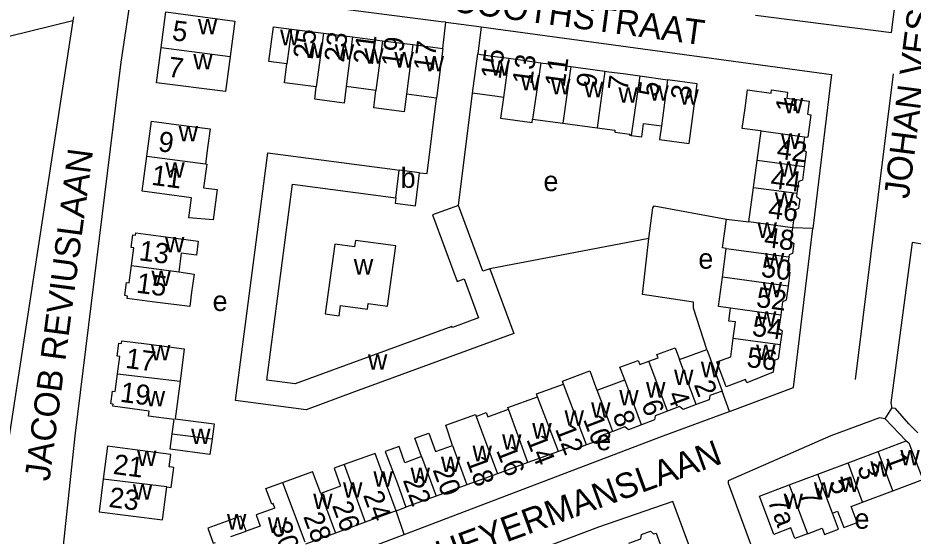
# Model space of a CAD drawing. Extents: x 161258 to 163262, y 380749 to 382054.
# Drawn here: x 161562.6 to 161740.8, y 381480.1 to 381583.2 of the extents above; entities that cross this region are included whole.
import ezdxf

# ---------------------------------------------------------------- set-up
doc = ezdxf.new("R2010")
doc.units = 0
for name, color, linetype in [('BLT_Basislijn', 7, 'Continuous'), ('BLT_Bebouwing', 7, 'Continuous'), ('BLT_Centroide', 7, 'Continuous'), ('BLT_Huisnummer', 7, 'Continuous'), ('BLT_Huisnummer_ tussenligend', 7, 'Continuous'), ('BLT_Onderverdeling_panden', 7, 'Continuous'), ('BLT_Straatnaam', 7, 'Continuous')]:
    doc.layers.add(name, color=color, linetype=linetype)

msp = doc.modelspace()

# ---------------------------------------------------------------- linework, layer by layer
at = {"layer": 'BLT_Basislijn'}
for p, q in [((161573.62, 381583.36), (161573.5, 381582.58)), ((161647.18, 381577.07), (161647.76, 381582.3)), ((161654.8, 381581.39), (161654.12, 381576)), ((161736.86, 381572.03), (161729.29, 381511.22)), ((161650.31, 381545.88), (161653.06, 381568.21)), ((161720.87, 381541.28), (161716.78, 381541.4)), ((161688.2, 381539.29), (161656.55, 381533.28)), ((161704.28, 381504.89), (161702.82, 381508.93)), ((161735.27, 381503.44), (161736.56, 381505.52)), ((161739.46, 381499.04), (161735.27, 381503.44)), ((161637.9, 381485.08), (161639.84, 381485.84)), ((161639.49, 381480.37), (161637.9, 381485.08))]:
    msp.add_line(p, q, dxfattribs=at)
for points in [[(161709.43, 381583.72), (161736.54, 381580.27), (161740.2, 381609.45)], [(161647.76, 381582.3), (161646.86, 381582.41), (161591.08, 381589.63), (161587.77, 381589.77), (161586.23, 381588.91), (161584.89, 381586.68), (161583.08, 381574.39), (161573.92, 381500), (161570.58, 381468.89), (161570.42, 381465.8), (161572.24, 381462.03), (161574.18, 381460.03), (161576.58, 381458.66), (161578.81, 381458.22), (161583.37, 381458.7), (161593.26, 381463), (161639.49, 381480.37)], [(161573.5, 381582.58), (161530.8, 381572.09), (161520.53, 381568.26), (161516.5, 381566.33)], [(161573.5, 381582.58), (161560.8, 381500), (161558.43, 381477.88), (161556.99, 381466.34), (161552.69, 381452.74), (161550.87, 381443.13)], [(161647.76, 381582.3), (161653.89, 381581.52), (161654.8, 381581.39)], [(161654.8, 381581.39), (161724.58, 381571.93), (161720.93, 381541.79), (161720.87, 381541.28)], [(161642.56, 381552.35), (161644.05, 381552.23), (161645.9, 381567.19)], [(161688.2, 381539.29), (161689.02, 381545.36), (161689.23, 381545.81), (161703.66, 381543.16)], [(161704.28, 381504.89), (161716.98, 381509.66), (161720.87, 381541.28)], [(161699.74, 381517.22), (161697.12, 381525.43), (161697.11, 381526.63), (161686.95, 381528.13), (161688.2, 381539.29)], [(161793.03, 381529.1), (161792.29, 381529.24), (161754.8, 381536.11), (161740.64, 381538.46), (161736.37, 381506.61), (161736.56, 381505.52)], [(161639.49, 381480.37), (161640.36, 381480.7), (161691.05, 381500), (161703.66, 381504.66), (161704.28, 381504.89)], [(161741.75, 381500.63), (161739.94, 381502.39), (161737.34, 381505.48), (161736.56, 381505.52)], [(161735.27, 381503.44), (161734.11, 381503.59), (161724.44, 381500), (161704.01, 381491.08), (161703.96, 381490.64), (161712.68, 381466.99), (161712.83, 381466.59)], [(161701.85, 381462.93), (161692.96, 381486.95), (161678.18, 381481.89), (161623.33, 381461.17), (161623.17, 381460.48), (161624.21, 381455.92), (161632.42, 381433.68), (161632.51, 381433.43)]]:
    msp.add_lwpolyline(points, dxfattribs=at)
at = {"layer": 'BLT_Bebouwing'}
for p, q in [((161617.02, 381580.95), (161623.39, 381580.15)), ((161623.39, 381580.15), (161629.21, 381579.4)), ((161629.21, 381579.4), (161635.14, 381578.63)), ((161635.14, 381578.63), (161641.2, 381577.85)), ((161641.2, 381577.85), (161647.18, 381577.07)), ((161647.18, 381577.07), (161645.9, 381567.19)), ((161653.06, 381568.21), (161654.12, 381576)), ((161633.86, 381568.75), (161627.93, 381569.52)), ((161709.77, 381554.82), (161710.57, 381560.69)), ((161719.21, 381559.54), (161719.86, 381559.45)), ((161709.05, 381549.44), (161709.77, 381554.82)), ((161642.56, 381552.35), (161638.51, 381552.88)), ((161708.12, 381542.57), (161709.05, 381549.44)), ((161702.84, 381531.62), (161703.61, 381537.31)), ((161694.28, 381515.2), (161699.74, 381517.22)), ((161677.88, 381509.1), (161683.4, 381511.15)), ((161733.84, 381496.92), (161739.46, 381499.04)), ((161670.19, 381496.92), (161664.13, 381494.71)), ((161727.86, 381494.67), (161733.84, 381496.92)), ((161633.72, 381496.51), (161627.51, 381494.3)), ((161664.13, 381494.71), (161658.05, 381492.49)), ((161721.85, 381492.4), (161727.86, 381494.67)), ((161615.23, 381490.73), (161621.26, 381492.93)), ((161658.05, 381492.49), (161651.95, 381490.26)), ((161716.14, 381490.25), (161721.85, 381492.4)), ((161651.95, 381490.26), (161645.84, 381488.03)), ((161736.75, 381489.1), (161742.73, 381491.35)), ((161645.84, 381488.03), (161639.84, 381485.84)), ((161730.77, 381486.84), (161736.75, 381489.1)), ((161637.9, 381485.08), (161631.71, 381482.82)), ((161631.71, 381482.82), (161625.77, 381480.65)), ((161625.77, 381480.65), (161619.84, 381478.48))]:
    msp.add_line(p, q, dxfattribs=at)
for points in [[(161591.06, 381577.29), (161592, 381584.35), (161605.75, 381582.53), (161604.81, 381575.47)], [(161616.12, 381574.05), (161612.55, 381574.51), (161613.45, 381581.41), (161617.02, 381580.95)], [(161604.81, 381575.47), (161603.89, 381568.51), (161590.13, 381570.23), (161591.06, 381577.29)], [(161654.12, 381576), (161654.76, 381575.92), (161657.52, 381575.51), (161660.29, 381575.14)], [(161615.63, 381570.25), (161616.12, 381574.05)], [(161660.29, 381575.14), (161660.7, 381575.08), (161663.57, 381574.68), (161666.71, 381574.26)], [(161666.71, 381574.26), (161667.11, 381574.2), (161669.65, 381573.89), (161672.64, 381573.49)], [(161672.64, 381573.49), (161679.45, 381572.56)], [(161679.45, 381572.56), (161680.22, 381572.46), (161683.06, 381572.09), (161686.37, 381571.64)], [(161686.37, 381571.64), (161691.94, 381570.88)], [(161621.98, 381569.43), (161615.63, 381570.25)], [(161690.7, 381561.7), (161690.33, 381559.01), (161696.22, 381558.21), (161697.16, 381565.13), (161697.84, 381570.08), (161691.94, 381570.88)], [(161627.93, 381569.52), (161627.51, 381566.24), (161621.69, 381567), (161621.98, 381569.43)], [(161639.92, 381567.97), (161639.47, 381564.49), (161633.41, 381565.28), (161633.86, 381568.75)], [(161659.23, 381567.37), (161658.01, 381567.53), (161653.06, 381568.21)], [(161710.57, 381560.69), (161709.87, 381560.79), (161706.8, 381561.14), (161707.35, 381565.22), (161707.85, 381568.86), (161712.53, 381568.23), (161712.61, 381568.85), (161715.81, 381568.42), (161715.64, 381567.2), (161720.12, 381566.59), (161719.78, 381564.01), (161720.46, 381563.92), (161719.86, 381559.45)], [(161645.9, 381567.19), (161639.92, 381567.97)], [(161659.23, 381567.37), (161658.67, 381563.23), (161664.93, 381562.38), (161665.02, 381563.05)], [(161665.02, 381563.05), (161671.09, 381562.23)], [(161588.25, 381555.66), (161589.18, 381562.64), (161594.08, 381561.99), (161600.83, 381561.09), (161600.39, 381557.81), (161599.9, 381554.11)], [(161671.09, 381562.23), (161677.92, 381561.3)], [(161677.92, 381561.3), (161681.45, 381560.82), (161681.4, 381560.45), (161684.38, 381560.05), (161684.35, 381559.83), (161684.65, 381559.78)], [(161684.65, 381559.78), (161686.77, 381559.49), (161687.14, 381562.19), (161690.7, 381561.7)], [(161719.21, 381559.54), (161718.87, 381557.04), (161719.53, 381556.53), (161719.13, 381553.56)], [(161599.9, 381554.11), (161600.15, 381554.08), (161599.53, 381549.4), (161602.26, 381549.04), (161601.46, 381542.99), (161596.58, 381543.43), (161597.1, 381547.39), (161587.33, 381548.69), (161588.25, 381555.66)], [(161629.59, 381508.75), (161619.94, 381505.22), (161605.9, 381507.05), (161612.34, 381556.3), (161637.6, 381553), (161638.51, 381552.88)], [(161637.8, 381547.39), (161637.66, 381546.34), (161641.7, 381545.81), (161642.56, 381552.35)], [(161719.13, 381553.56), (161718.77, 381550.92), (161718, 381550.6), (161717.69, 381548.28)], [(161650.31, 381545.88), (161645.13, 381543.98), (161650, 381530.7), (161651.45, 381531.23), (161654.29, 381523.48), (161649.09, 381521.57), (161649, 381521.8), (161617.76, 381510.35), (161612.11, 381511.09), (161617.21, 381550.09), (161637.8, 381547.39)], [(161717.69, 381548.28), (161717.6, 381547.62), (161718.25, 381547.11), (161718, 381545.25), (161717.27, 381544.95), (161716.78, 381541.4)], [(161656.55, 381533.28), (161655.12, 381532.76), (161650.31, 381545.88)], [(161703.61, 381537.31), (161702.88, 381537.41), (161703.66, 381543.16)], [(161703.66, 381543.16), (161708.12, 381542.57)], [(161716.78, 381541.4), (161716.43, 381538.76), (161717.06, 381538.28), (161716.79, 381536.31), (161716.11, 381536.03), (161716.06, 381535.64)], [(161585.19, 381533.93), (161585.65, 381537.41), (161585.09, 381537.49), (161585.43, 381540.02), (161585.99, 381539.95), (161586.05, 381540.4), (161591.04, 381539.74), (161598.46, 381538.76), (161598.1, 381535.99), (161595.1, 381536.39), (161594.61, 381532.68)], [(161623.74, 381524.3), (161626.52, 381523.92), (161626.8, 381525.97), (161632.15, 381525.24), (161632.3, 381526.33), (161636.16, 381525.8), (161637.81, 381537.82), (161629.78, 381538.92), (161629.6, 381537.64), (161625.65, 381538.18), (161623.74, 381524.3)], [(161716.06, 381535.64), (161715.71, 381533.03), (161716.28, 381532.59), (161715.91, 381529.8)], [(161594.61, 381532.68), (161597.67, 381532.21), (161597.16, 381528.58), (161596.78, 381525.73), (161589.29, 381526.72), (161584.33, 381527.38), (161584.39, 381527.84), (161583.83, 381527.92), (161584.18, 381530.51), (161584.73, 381530.44), (161585.19, 381533.93)], [(161656.55, 381533.28), (161658.27, 381528.59), (161661.28, 381520.36), (161629.59, 381508.75)], [(161704.47, 381525.44), (161702.05, 381525.76), (161702.84, 381531.62)], [(161715.91, 381529.8), (161715.53, 381527), (161714.81, 381526.71), (161714.45, 381524.04)], [(161704.99, 381519.45), (161705.42, 381522.68), (161704.12, 381522.85), (161704.47, 381525.44)], [(161714.45, 381524.04), (161714.09, 381521.38), (161714.73, 381520.89), (161714.36, 381518.2)], [(161582.37, 381512.33), (161582.83, 381515.82), (161582.32, 381515.89), (161582.66, 381518.48), (161583.18, 381518.41), (161583.25, 381518.96), (161588.18, 381518.31), (161595.68, 381517.32), (161594.88, 381510.91)], [(161714.36, 381518.2), (161713.97, 381515.32), (161713.24, 381515.02), (161712.92, 381512.71), (161707.72, 381510.57), (161707.45, 381511.22), (161703.6, 381509.78), (161701.75, 381514.78), (161704.5, 381515.75), (161704.99, 381519.45)], [(161688.22, 381514.89), (161690.04, 381515.56), (161689.81, 381516.18), (161693.42, 381517.52), (161694.28, 381515.2)], [(161699.74, 381517.22), (161701.08, 381513.62), (161702.82, 381508.93)], [(161683.4, 381511.15), (161682.45, 381513.7), (161686.06, 381515.04), (161686.37, 381514.2), (161688.21, 381514.88)], [(161671.22, 381510.33), (161671, 381510.92), (161676.42, 381512.97), (161677.84, 381509.09), (161677.88, 381509.1)], [(161593.29, 381500.44), (161593.66, 381503.25), (161588.59, 381503.92), (161588.73, 381504.96), (161581.49, 381505.92), (161581.55, 381506.31), (161581.04, 381506.38), (161581.37, 381508.9), (161581.9, 381508.83), (161582.37, 381512.33)], [(161594.88, 381510.91), (161593.89, 381503.39), (161601.62, 381502.41), (161601.22, 381499.44)], [(161666.05, 381507.8), (161665.85, 381508.36), (161671.22, 381510.33)], [(161660.26, 381505.32), (161660.14, 381505.65), (161666.05, 381507.8)], [(161702.82, 381508.93), (161700.35, 381508.02), (161700.21, 381507.2), (161697.61, 381506.24)], [(161697.61, 381506.24), (161695.01, 381505.27), (161694.32, 381505.84), (161691.89, 381504.93)], [(161649.08, 381498.1), (161647.76, 381502.15), (161653.69, 381504.27), (161653.82, 381503.89)], [(161653.82, 381503.89), (161655.8, 381504.66), (161656.12, 381503.8), (161660.26, 381505.32)], [(161691.89, 381504.93), (161689.45, 381504.03), (161689.31, 381503.18), (161686.72, 381502.22)], [(161686.72, 381502.22), (161684.12, 381501.25), (161683.42, 381501.84), (161681.03, 381500.92)], [(161601.22, 381499.44), (161600.81, 381496.31), (161592.88, 381497.36), (161593.29, 381500.44)], [(161642.96, 381495.91), (161641.63, 381499.56), (161644.41, 381500.57), (161645.74, 381496.92), (161649.08, 381498.1)], [(161681.03, 381500.92), (161678.65, 381500), (161678.54, 381499.22), (161675.78, 381498.22)], [(161739.46, 381499.04), (161739.99, 381498.61), (161741.76, 381493.93), (161742.73, 381491.35)], [(161592.2, 381489.9), (161593.07, 381489.78), (161593.58, 381493.73), (161592.67, 381493.85), (161592.99, 381496.33), (161585.4, 381497.3), (161580.4, 381497.94), (161579.57, 381491.44)], [(161642.96, 381495.91), (161639.64, 381494.68), (161638.46, 381497.9), (161635.66, 381496.88), (161638.12, 381490.53), (161639.84, 381485.84)], [(161675.78, 381498.22), (161673.36, 381497.33), (161672.74, 381497.85), (161670.19, 381496.92)], [(161637.9, 381485.08), (161636.18, 381489.77), (161633.72, 381496.51)], [(161627.51, 381494.3), (161625.52, 381493.57), (161626.82, 381490.01), (161622.88, 381488.57)], [(161579.57, 381491.44), (161578.73, 381484.91), (161591.36, 381483.29), (161591.42, 381483.76), (161592.2, 381489.9)], [(161622.88, 381488.57), (161621.25, 381492.93)], [(161613.71, 381485.64), (161613.41, 381486.55), (161613.1, 381486.44), (161611.96, 381489.54), (161615.23, 381490.73)], [(161719.81, 381480.54), (161717.28, 381479.59), (161716.48, 381481.71), (161713.08, 381480.43), (161710.21, 381488.02), (161716.14, 381490.25)], [(161724.76, 381484.67), (161725.77, 381485.05), (161727, 381481.8), (161729.65, 381482.8), (161728.45, 381485.97), (161730.77, 381486.84)], [(161613.71, 381485.64), (161609.98, 381484.28), (161610.78, 381482.09)], [(161719.81, 381480.54), (161722.68, 381481.68), (161723.17, 381480.38), (161725.98, 381481.43), (161724.76, 381484.67)], [(161608.01, 381481.08), (161606.93, 381484.05), (161600.37, 381481.65), (161601.45, 381478.68), (161601.88, 381478.84)], [(161610.78, 381482.09), (161608.01, 381481.08)], [(161684.21, 381478.67), (161686.59, 381479.56), (161686.73, 381480.39), (161688.53, 381481.05), (161689.15, 381480.53), (161689.63, 381480.66), (161691.23, 381476.29)]]:
    msp.add_lwpolyline(points, dxfattribs=at)
at = {"layer": 'BLT_Onderverdeling_panden'}
for p, q in [((161617.02, 381580.95), (161616.12, 381574.05)), ((161623.39, 381580.15), (161621.98, 381569.43)), ((161629.21, 381579.4), (161627.93, 381569.52)), ((161591.06, 381577.29), (161604.81, 381575.47)), ((161635.14, 381578.63), (161633.86, 381568.75)), ((161641.2, 381577.85), (161639.92, 381567.97)), ((161660.29, 381575.14), (161659.23, 381567.37)), ((161666.71, 381574.26), (161665.02, 381563.05)), ((161672.64, 381573.49), (161671.09, 381562.23)), ((161679.45, 381572.56), (161677.92, 381561.3)), ((161686.37, 381571.64), (161684.65, 381559.78)), ((161691.94, 381570.88), (161690.7, 381561.7)), ((161710.57, 381560.69), (161719.21, 381559.54)), ((161588.25, 381555.66), (161599.9, 381554.11)), ((161719.13, 381553.56), (161709.77, 381554.82)), ((161637.8, 381547.39), (161638.51, 381552.88)), ((161709.05, 381549.44), (161717.69, 381548.28)), ((161716.78, 381541.4), (161708.12, 381542.57)), ((161703.61, 381537.31), (161716.06, 381535.64)), ((161585.19, 381533.93), (161594.61, 381532.68)), ((161715.91, 381529.8), (161702.84, 381531.62)), ((161714.45, 381524.04), (161704.47, 381525.44)), ((161704.99, 381519.45), (161714.36, 381518.2)), ((161691.89, 381504.93), (161688.21, 381514.88)), ((161697.61, 381506.24), (161694.28, 381515.2)), ((161582.37, 381512.33), (161594.88, 381510.91)), ((161686.72, 381502.22), (161683.4, 381511.15)), ((161675.78, 381498.22), (161671.22, 381510.33)), ((161670.19, 381496.92), (161666.05, 381507.8)), ((161681.03, 381500.92), (161677.88, 381509.1)), ((161653.82, 381503.89), (161658.05, 381492.49)), ((161664.13, 381494.71), (161660.26, 381505.32)), ((161593.29, 381500.44), (161601.22, 381499.44)), ((161649.08, 381498.1), (161651.95, 381490.26)), ((161736.75, 381489.1), (161733.84, 381496.92)), ((161642.96, 381495.91), (161645.84, 381488.03)), ((161627.51, 381494.3), (161631.71, 381482.82)), ((161730.77, 381486.84), (161727.86, 381494.67)), ((161592.2, 381489.9), (161579.57, 381491.44)), ((161724.76, 381484.67), (161721.85, 381492.4)), ((161615.23, 381490.73), (161619.67, 381478.94)), ((161716.14, 381490.25), (161719.81, 381480.54)), ((161622.88, 381488.57), (161625.77, 381480.65))]:
    msp.add_line(p, q, dxfattribs=at)
msp.add_lwpolyline([(161604.97, 381479.97), (161608.01, 381481.08)], dxfattribs=at)

# ---------------------------------------------------------------- texts
at = {"layer": 'BLT_Centroide'}
for s, p in [('w', (161598.41, 381579.91)), ('w', (161614.78, 381577.73)), ('w', (161619.52, 381575.19)), ('w', (161625.66, 381574.84)), ('w', (161631.53, 381574.08)), ('w', (161597.48, 381572.91)), ('w', (161637.53, 381573.3)), ('w', (161643.55, 381572.52)), ('w', (161656.67, 381571.67)), ('w', (161662.69, 381568.75)), ('w', (161668.73, 381567.94)), ('w', (161675.27, 381567.39)), ('w', (161682.14, 381566.28)), ('w', (161688.3, 381566.7)), ('w', (161694.27, 381565.89)), ('w', (161715.06, 381564.16)), ('w', (161594.57, 381558.59)), ('w', (161714.48, 381557.12)), ('w', (161591.91, 381551.38)), ('w', (161714.09, 381551.56)), ('b', (161638.78, 381549.36)), ('e', (161667.22, 381548.71)), ('w', (161713.26, 381545.41)), ('w', (161709.83, 381539.41)), ('w', (161591.85, 381536.53)), ('e', (161698.06, 381533.28)), ('w', (161711.3, 381533.31)), ('w', (161629.45, 381532.11)), ('w', (161589.16, 381529.81)), ('w', (161710.85, 381527.56)), ('e', (161601.33, 381524.86)), ('w', (161709.72, 381521.72)), ('w', (161709.56, 381515.09)), ('w', (161589.05, 381515.03)), ('w', (161632.26, 381513.19)), ('w', (161698.55, 381511.69)), ('w', (161693.22, 381510.12)), ('w', (161687.64, 381507.64)), ('w', (161588.02, 381505.88)), ('w', (161682.3, 381506.08)), ('w', (161676.7, 381503.61)), ('w', (161671.41, 381502.03)), ('w', (161664.98, 381499.48)), ('w', (161597.05, 381498.38)), ('w', (161658.97, 381497.28)), ('e', (161677.73, 381497.16)), ('w', (161586.3, 381494.03)), ('w', (161653.09, 381494.97)), ('w', (161738.28, 381494.14)), ('w', (161646.8, 381492.83)), ('w', (161732.3, 381491.89)), ('w', (161640.75, 381490.62)), ('w', (161633.36, 381489.89)), ('w', (161726.31, 381488.86)), ('w', (161585.46, 381487.31)), ('w', (161627.3, 381487.7)), ('w', (161721.06, 381487.72)), ('w', (161621.36, 381485.48)), ('w', (161715.02, 381485.48)), ('w', (161604.19, 381481.38)), ('e', (161729.16, 381481.54)), ('w', (161612.33, 381480.73))]:
    msp.add_text(s, height=4, dxfattribs=at).set_placement(p)
at = {"layer": 'BLT_Huisnummer'}
for s, rotation, p in [('5', 352.4569, (161593.12, 381578.77)), ('25', 82.6774, (161621.28, 381574.83)), ('21', 82.6738, (161633.24, 381573.74)), ('17', 82.6254, (161645.27, 381572.42)), ('7', 352.4524, (161592.31, 381571.52)), ('15', 82.2839, (161658.67, 381570.84)), ('11', 82.2888, (161671.41, 381569.25)), ('7', 82.2881, (161683.94, 381568.49)), ('3', 82.2637, (161696.44, 381566.66)), ('1', 82.2961, (161717.34, 381564.25)), ('9', 352.4565, (161590.35, 381556.69)), ('42', 352.3884, (161713.52, 381555.21)), ('11', 352.4614, (161589.01, 381549.99)), ('46', 352.2989, (161711.8, 381543.39)), ('13', 352.4548, (161586.52, 381534.99)), ('50', 352.297, (161710.39, 381531.71)), ('15', 352.4519, (161586, 381528.54)), ('17', 352.4526, (161583.83, 381513.57)), ('56', 352.3849, (161707.54, 381513.77)), ('2', 290.3782, (161697.12, 381510.23)), ('19', 352.45, (161582.77, 381506.83)), ('6', 290.378, (161686.65, 381506.39)), ('10', 291.1022, (161675.06, 381503.34)), ('14', 291.3714, (161663.75, 381499.33)), ('21', 352.6977, (161581.38, 381492.46)), ('18', 290.077, (161651.77, 381495.18)), ('1', 290.4166, (161735.35, 381495.76)), ('22', 290.0693, (161639.17, 381491.25)), ('5', 290.629, (161724.02, 381490.8)), ('23', 352.6991, (161580.52, 381485.9)), ('7', 290.6755, (161718.12, 381488.56)), ('7a', 290.6593, (161711.79, 381487.14)), ('26', 290.0725, (161625.07, 381486.19)), ('30', 290.072, (161612.95, 381482.2))]:
    msp.add_text(s, height=4, rotation=rotation, dxfattribs=at).set_placement(p)
at = {"layer": 'BLT_Huisnummer_ tussenligend'}
for s, rotation, p in [('23', 82.6738, (161627.48, 381574.21)), ('19', 82.6254, (161638.86, 381573.25)), ('13', 82.2888, (161664.94, 381569.76)), ('9', 82.2881, (161677.66, 381569.05)), ('5', 82.2637, (161690.02, 381567.35)), ('44', 352.3884, (161712.28, 381549.35)), ('48', 352.2989, (161710.99, 381537.65)), ('52', 352.297, (161709.44, 381525.7)), ('54', 352.297, (161708.61, 381519.96)), ('4', 290.3782, (161691.79, 381508.2)), ('8', 290.378, (161680.92, 381504.19)), ('12', 291.1022, (161669.47, 381501.42)), ('16', 291.3714, (161657.75, 381497.15)), ('20', 290.077, (161645.12, 381493.28)), ('3', 290.4166, (161729.6, 381493.72)), ('24', 290.0693, (161631.25, 381488.26)), ('28', 290.0725, (161619.34, 381484))]:
    msp.add_text(s, height=4, rotation=rotation, dxfattribs=at).set_placement(p)
at = {"layer": 'BLT_Straatnaam'}
for s, rotation, p in [('JOHAN VESTERSSTRAAT', 82.7626, (161739.95, 381547.04)), ('VAN COOTHSTRAAT', 352.3352, (161633.39, 381586.54)), ('JACOB REVIUSLAAN', 82.4859, (161568.84, 381490.86)), ('HERMAN HEYERMANSLAAN', 20.0858, (161617.95, 381463.5))]:
    msp.add_text(s, height=5, rotation=rotation, dxfattribs=at).set_placement(p)

doc.saveas('drawing.dxf')
